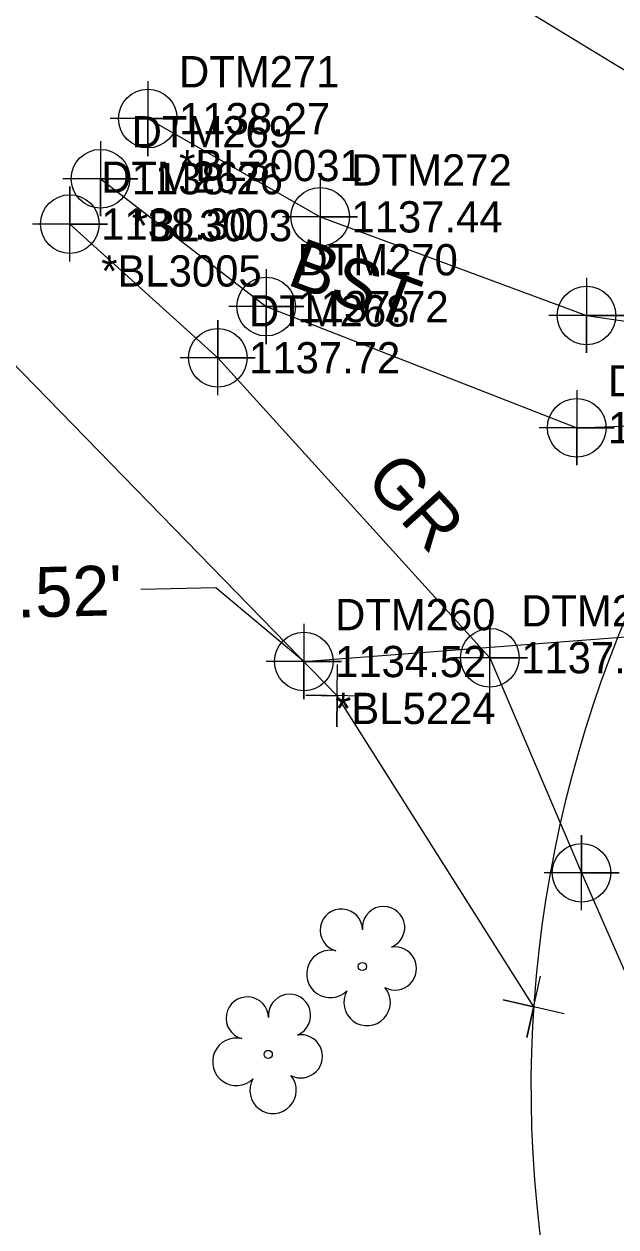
# Model space of a CAD drawing. Extents: x 1286007 to 1287145, y 857718 to 858514.
# Drawn here: x 1286447.6 to 1286494.9, y 858055.9 to 858152 of the extents above; entities that cross this region are included whole.
import ezdxf

# ---------------------------------------------------------------- set-up
doc = ezdxf.new("R2010")
doc.units = 0
for name, color, linetype in [('Default', 7, 'Continuous'), ('Exist Property Corner CELL', 7, 'Continuous'), ('Exist Property Line', 7, 'Continuous'), ('Exist Right of Way Line', 7, 'Continuous'), ('Exist Roads EOP Other', 7, 'Continuous'), ('Exist Roads EOP Other Cogo Comment', 7, 'Continuous'), ('Exist Roads EOP Other Cogo Elevation', 7, 'Continuous'), ('Exist Roads EOP Other Cogo Number', 7, 'Continuous'), ('Exist Roads EOP Other Cogo Point CELL', 7, 'Continuous'), ('Exist Roads EOP Other Text', 7, 'Continuous'), ('Exist Roads Soil', 7, 'Continuous'), ('Exist Roads Soil Cogo Comment', 7, 'Continuous'), ('Exist Roads Soil Cogo Elevation', 7, 'Continuous'), ('Exist Roads Soil Cogo Number', 7, 'Continuous'), ('Exist Roads Soil Cogo Point CELL', 7, 'Continuous'), ('Exist Roads Soil Text', 7, 'Continuous'), ('Exist Structure Minor Pipes CMP 24 Inch', 7, 'Continuous'), ('Exist Structure Minor Pipes CMP 24 Inch Cogo Comment', 7, 'Continuous'), ('Exist Structure Minor Pipes CMP 24 Inch Cogo Elevation', 7, 'Continuous'), ('Exist Structure Minor Pipes CMP 24 Inch Cogo Number', 7, 'Continuous'), ('Exist Structure Minor Pipes CMP 24 Inch Cogo Point CELL', 7, 'Continuous'), ('Exist Structure Minor Pipes CMP 24 Inch Invert', 7, 'Continuous'), ('Exist Vegetation Tree CELL', 7, 'Continuous')]:
    doc.layers.add(name, color=color, linetype=linetype)

msp = doc.modelspace()

# ---------------------------------------------------------------- linework, layer by layer
at = {"layer": 'Default'}
msp.add_line((1286521.306, 858132.586), (1286424.588, 858191.789), dxfattribs=at)
at = {"layer": 'Exist Property Corner CELL'}
for p, q in [((1286472.625, 858098.34), (1286472.625, 858098.34)), ((1286488.342, 858073.469), (1286488.342, 858073.469))]:
    msp.add_line(p, q, dxfattribs=at)
for points in [[(1286475.125, 858098.309), (1286470.126, 858098.372), (1286472.625, 858098.34), (1286472.594, 858095.841), (1286472.657, 858100.84)], [(1286490.781, 858072.919), (1286485.903, 858074.019), (1286488.342, 858073.469), (1286487.792, 858071.03), (1286488.892, 858075.908)]]:
    msp.add_lwpolyline(points, dxfattribs=at)
at = {"layer": 'Exist Property Line'}
for p, q in [((1286472.625, 858098.34), (1286425.303, 858146.88)), ((1286488.342, 858073.469), (1286472.625, 858098.34))]:
    msp.add_line(p, q, dxfattribs=at)
at = {"layer": 'Exist Right of Way Line'}
msp.add_arc((1286585.125, 858066.987), 97, 115.04397, 191.72533, dxfattribs=at)
at = {"layer": 'Exist Roads EOP Other'}
for points in [[(1286457.489, 858144.476), (1286471.264, 858136.623), (1286492.557, 858128.739), (1286511.821, 858125.921), (1286519.793, 858124.78)], [(1286453.703, 858139.674), (1286466.954, 858129.445), (1286491.774, 858119.764), (1286512.279, 858120.499), (1286519.796, 858124.783)]]:
    msp.add_lwpolyline(points, dxfattribs=at)
at = {"layer": 'Exist Roads EOP Other Cogo Point CELL'}
for points in [[(1286457.489, 858147.476), (1286457.489, 858141.476), (1286457.489, 858144.476), (1286460.489, 858144.476), (1286454.489, 858144.476)], [(1286453.703, 858142.674), (1286453.703, 858136.674), (1286453.703, 858139.674), (1286456.703, 858139.674), (1286450.703, 858139.674)], [(1286471.264, 858139.623), (1286471.264, 858133.623), (1286471.264, 858136.623), (1286474.264, 858136.623), (1286468.264, 858136.623)], [(1286466.954, 858132.445), (1286466.954, 858126.445), (1286466.954, 858129.445), (1286469.954, 858129.445), (1286463.954, 858129.445)], [(1286492.557, 858131.739), (1286492.557, 858125.739), (1286492.557, 858128.739), (1286495.557, 858128.739), (1286489.557, 858128.739)], [(1286491.774, 858122.764), (1286491.774, 858116.764), (1286491.774, 858119.764), (1286494.774, 858119.764), (1286488.774, 858119.764)]]:
    msp.add_lwpolyline(points, dxfattribs=at)
for centre in [(1286457.489, 858144.476), (1286453.703, 858139.674), (1286471.264, 858136.623), (1286466.954, 858129.445), (1286492.557, 858128.739), (1286491.774, 858119.764)]:
    msp.add_circle(centre, 2.344, dxfattribs=at)
at = {"layer": 'Exist Roads Soil'}
msp.add_lwpolyline([(1286451.264, 858136.048), (1286463.084, 858125.359), (1286484.836, 858101.378), (1286492.165, 858084.188), (1286501.894, 858062.005)], dxfattribs=at)
at = {"layer": 'Exist Roads Soil Cogo Point CELL'}
for points in [[(1286451.264, 858133.048), (1286451.264, 858139.048), (1286451.264, 858136.048), (1286454.264, 858136.048), (1286448.264, 858136.048)], [(1286463.084, 858122.359), (1286463.084, 858128.359), (1286463.084, 858125.359), (1286466.084, 858125.359), (1286460.084, 858125.359)], [(1286484.836, 858098.378), (1286484.836, 858104.378), (1286484.836, 858101.378), (1286487.836, 858101.378), (1286481.836, 858101.378)], [(1286492.165, 858081.188), (1286492.165, 858087.188), (1286492.165, 858084.188), (1286495.165, 858084.188), (1286489.165, 858084.188)]]:
    msp.add_lwpolyline(points, dxfattribs=at)
for centre in [(1286451.264, 858136.048), (1286463.084, 858125.359), (1286484.836, 858101.378), (1286492.165, 858084.188)]:
    msp.add_circle(centre, 2.344, dxfattribs=at)
at = {"layer": 'Exist Structure Minor Pipes CMP 24 Inch'}
msp.add_line((1286469.96, 858101.075), (1286559.538, 858107.984), dxfattribs=at)
at = {"layer": 'Exist Structure Minor Pipes CMP 24 Inch Cogo Point CELL'}
msp.add_lwpolyline([(1286469.96, 858104.075), (1286469.96, 858098.075), (1286469.96, 858101.075), (1286472.96, 858101.075), (1286466.96, 858101.075)], dxfattribs=at)
msp.add_circle((1286469.96, 858101.075), 2.344, dxfattribs=at)
at = {"layer": 'Exist Structure Minor Pipes CMP 24 Inch Invert'}
msp.add_lwpolyline([(1286469.96, 858101.075), (1286462.922, 858106.966), (1286456.924, 858106.82)], dxfattribs=at)
at = {"layer": 'Exist Vegetation Tree CELL'}
for p, q in [((1286474.637, 858076.69), (1286474.637, 858076.69)), ((1286467.118, 858069.665), (1286467.118, 858069.665))]:
    msp.add_line(p, q, dxfattribs=at)
for centre in [(1286474.637, 858076.69), (1286467.118, 858069.665)]:
    msp.add_circle(centre, 0.326, dxfattribs=at)
for centre, radius, start, end in [((1286472.964, 858079.589), 1.698, 1.28216, 254.55999), ((1286476.341, 858079.811), 1.689, 291.56708, 186.23104), ((1286472.088, 858076.101), 1.899, 77.1011, 314.19993), ((1286477.242, 858076.536), 1.727, 242.66361, 99.3457), ((1286475.022, 858073.816), 1.856, 150.16508, 39.71335), ((1286465.446, 858072.565), 1.698, 1.28216, 254.55999), ((1286468.823, 858072.786), 1.689, 291.56708, 186.23104), ((1286469.724, 858069.511), 1.727, 242.66361, 99.3457), ((1286464.57, 858069.077), 1.899, 77.1011, 314.19993), ((1286467.503, 858066.792), 1.856, 150.16508, 39.71335)]:
    msp.add_arc(centre, radius, start, end, dxfattribs=at)

# ---------------------------------------------------------------- texts
at = {"layer": 'Exist Roads EOP Other Cogo Comment'}
for s, p in [('*BL30031', (1286459.989, 858139.476)), ('*BL3003', (1286456.203, 858134.674))]:
    msp.add_text(s, height=2.5, dxfattribs=at).set_placement(p)
at = {"layer": 'Exist Roads EOP Other Cogo Elevation'}
for s, p in [('1138.27', (1286459.989, 858143.226)), ('1138.26', (1286456.203, 858138.424)), ('1137.44', (1286473.764, 858135.373)), ('1137.72', (1286469.454, 858128.195)), ('1136.83', (1286494.274, 858118.514))]:
    msp.add_text(s, height=2.5, dxfattribs=at).set_placement(p)
at = {"layer": 'Exist Roads EOP Other Cogo Number'}
for s, p in [('DTM271', (1286459.989, 858146.976)), ('DTM269', (1286456.203, 858142.174)), ('DTM272', (1286473.764, 858139.123)), ('DTM270', (1286469.454, 858131.945)), ('DTM275', (1286494.274, 858122.264))]:
    msp.add_text(s, height=2.5, dxfattribs=at).set_placement(p)
at = {"layer": 'Exist Roads EOP Other Text'}
msp.add_text('BST', height=4, rotation=339.6823, dxfattribs=at).set_placement((1286468.503, 858131.247))
at = {"layer": 'Exist Roads Soil Cogo Comment'}
msp.add_text('*BL3005', height=2.5, dxfattribs=at).set_placement((1286453.764, 858131.048))
at = {"layer": 'Exist Roads Soil Cogo Elevation'}
for s, p in [('1138.30', (1286453.764, 858134.798)), ('1137.72', (1286465.584, 858124.109)), ('1137.30', (1286487.336, 858100.128))]:
    msp.add_text(s, height=2.5, dxfattribs=at).set_placement(p)
at = {"layer": 'Exist Roads Soil Cogo Number'}
for s, p in [('DTM267', (1286453.764, 858138.548)), ('DTM268', (1286465.584, 858127.859)), ('DTM279', (1286487.336, 858103.878))]:
    msp.add_text(s, height=2.5, dxfattribs=at).set_placement(p)
at = {"layer": 'Exist Roads Soil Text'}
msp.add_text('GR', height=4, rotation=312.20964, dxfattribs=at).set_placement((1286474.738, 858115.488))
at = {"layer": 'Exist Structure Minor Pipes CMP 24 Inch Cogo Comment'}
msp.add_text('*BL5224', height=2.5, dxfattribs=at).set_placement((1286472.46, 858096.075))
at = {"layer": 'Exist Structure Minor Pipes CMP 24 Inch Cogo Elevation'}
msp.add_text('1134.52', height=2.5, dxfattribs=at).set_placement((1286472.46, 858099.825))
at = {"layer": 'Exist Structure Minor Pipes CMP 24 Inch Cogo Number'}
msp.add_text('DTM260', height=2.5, dxfattribs=at).set_placement((1286472.46, 858103.575))
at = {"layer": 'Exist Structure Minor Pipes CMP 24 Inch Invert'}
msp.add_text("INV=1134.52'", height=4, rotation=1.39272, dxfattribs=at).set_placement((1286423.109, 858103.997))

doc.saveas('drawing.dxf')
